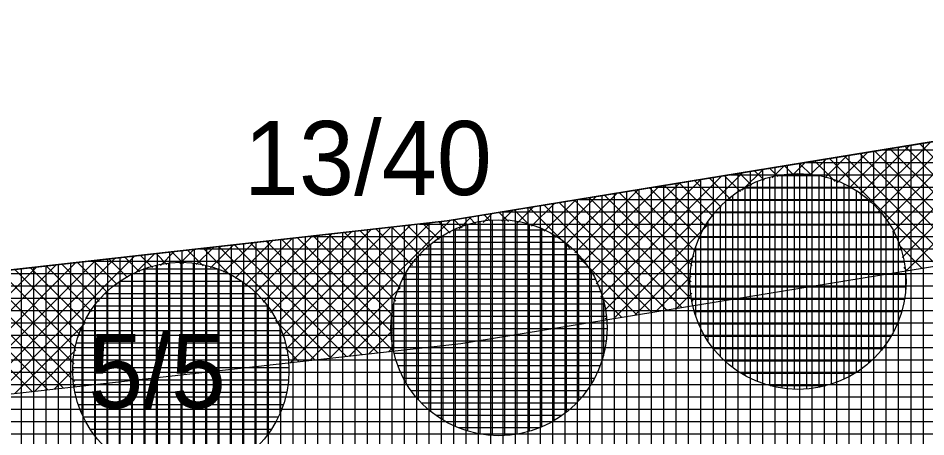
# Model space of a CAD drawing. Extents: x -566461 to -565198, y -1096301 to -1095707.
# Drawn here: x -565594.91 to -565580.22, y -1095872.26 to -1095865.47 of the extents above; entities that cross this region are included whole.
import ezdxf

# ---------------------------------------------------------------- set-up
doc = ezdxf.new("R2010")
doc.units = 0
for name, color, linetype in [('Vrstva 13', 7, 'Continuous'), ('Vrstva 40', 7, 'Continuous'), ('Vrstva 41', 7, 'Continuous'), ('Vrstva 42', 7, 'Continuous'), ('Vrstva 43', 7, 'Continuous'), ('Vrstva 44', 7, 'Continuous')]:
    doc.layers.add(name, color=color, linetype=linetype)

msp = doc.modelspace()

# ---------------------------------------------------------------- linework, layer by layer
at = {"layer": 'Vrstva 13'}
for p, q in [((-565587.97, -1095868.76), (-565569.62, -1095865.76)), ((-565610.5, -1095871.29), (-565587.97, -1095868.76))]:
    msp.add_line(p, q, dxfattribs=at)
at = {"layer": 'Vrstva 41'}
for p, q in [((-565580.604, -1095869.354), (-565578.455, -1095867.204)), ((-565580.538, -1095869.57), (-565578.117, -1095867.149)), ((-565580.862, -1095868.763), (-565579.469, -1095867.37)), ((-565580.757, -1095868.941), (-565579.131, -1095867.315)), ((-565580.67, -1095869.137), (-565578.793, -1095867.26)), ((-565581.125, -1095868.46), (-565580.145, -1095867.481)), ((-565580.985, -1095868.604), (-565579.807, -1095867.425)), ((-565578.577, -1095869.25), (-565580.318, -1095867.509)), ((-565581.648, -1095868.135), (-565581.16, -1095867.647)), ((-565581.455, -1095868.225), (-565580.822, -1095867.591)), ((-565579.55, -1095869.409), (-565581.291, -1095867.668)), ((-565581.281, -1095868.333), (-565580.484, -1095867.536)), ((-565579.307, -1095869.369), (-565581.048, -1095867.628)), ((-565579.064, -1095869.329), (-565580.805, -1095867.589)), ((-565578.82, -1095869.29), (-565580.561, -1095867.549)), ((-565582.375, -1095868.013), (-565582.174, -1095867.812)), ((-565582.099, -1095868.02), (-565581.836, -1095867.757)), ((-565581.688, -1095868.119), (-565582.02, -1095867.787)), ((-565581.861, -1095868.065), (-565581.498, -1095867.702)), ((-565580.036, -1095869.488), (-565581.777, -1095867.748)), ((-565579.793, -1095869.449), (-565581.534, -1095867.708)), ((-565583.191, -1095868.263), (-565582.85, -1095867.923)), ((-565582.839, -1095868.099), (-565582.992, -1095867.946)), ((-565582.615, -1095868.041), (-565582.749, -1095867.906)), ((-565582.707, -1095868.062), (-565582.512, -1095867.868)), ((-565582.36, -1095868.013), (-565582.506, -1095867.867)), ((-565582.065, -1095868.025), (-565582.263, -1095867.827)), ((-565585.555, -1095869.779), (-565583.865, -1095868.089)), ((-565585.479, -1095869.986), (-565583.527, -1095868.034)), ((-565585.426, -1095870.216), (-565583.188, -1095867.978)), ((-565583.532, -1095868.537), (-565583.965, -1095868.105)), ((-565583.385, -1095868.402), (-565583.722, -1095868.065)), ((-565583.221, -1095868.283), (-565583.479, -1095868.026)), ((-565583.04, -1095868.182), (-565583.236, -1095867.986)), ((-565585.902, -1095869.278), (-565584.879, -1095868.255)), ((-565585.77, -1095869.428), (-565584.541, -1095868.199)), ((-565585.654, -1095869.595), (-565584.203, -1095868.144)), ((-565583.875, -1095869.044), (-565584.694, -1095868.224)), ((-565583.778, -1095868.857), (-565584.451, -1095868.185)), ((-565583.664, -1095868.689), (-565584.208, -1095868.145)), ((-565586.216, -1095869.026), (-565585.555, -1095868.365)), ((-565586.051, -1095869.143), (-565585.217, -1095868.31)), ((-565583.989, -1095870.061), (-565585.666, -1095868.383)), ((-565584.021, -1095869.746), (-565585.423, -1095868.344)), ((-565584, -1095869.484), (-565585.18, -1095868.304)), ((-565583.949, -1095869.253), (-565584.937, -1095868.264)), ((-565586.829, -1095868.791), (-565586.57, -1095868.531)), ((-565585.981, -1095869.2), (-565586.639, -1095868.542)), ((-565586.601, -1095868.846), (-565586.232, -1095868.476)), ((-565586.399, -1095868.926), (-565585.893, -1095868.421)), ((-565584.655, -1095870.243), (-565586.396, -1095868.503)), ((-565584.412, -1095870.203), (-565586.153, -1095868.463)), ((-565584.169, -1095870.164), (-565585.91, -1095868.423)), ((-565587.777, -1095868.89), (-565587.584, -1095868.697)), ((-565587.388, -1095868.784), (-565587.246, -1095868.642)), ((-565587.261, -1095868.769), (-565587.368, -1095868.662)), ((-565586.977, -1095868.77), (-565587.125, -1095868.622)), ((-565587.086, -1095868.764), (-565586.908, -1095868.586)), ((-565586.625, -1095868.839), (-565586.882, -1095868.582)), ((-565590.581, -1095870.845), (-565588.562, -1095868.826)), ((-565590.51, -1095871.057), (-565588.244, -1095868.791)), ((-565590.192, -1095871.022), (-565587.922, -1095868.752)), ((-565588.26, -1095869.184), (-565588.612, -1095868.832)), ((-565588.099, -1095869.062), (-565588.358, -1095868.804)), ((-565587.922, -1095868.957), (-565588.103, -1095868.775)), ((-565587.725, -1095868.87), (-565587.854, -1095868.741)), ((-565587.508, -1095868.805), (-565587.611, -1095868.701)), ((-565585.271, -1095870.343), (-565583.767, -1095868.839)), ((-565590.945, -1095870.078), (-565589.837, -1095868.97)), ((-565590.826, -1095870.242), (-565589.518, -1095868.934)), ((-565590.724, -1095870.422), (-565589.199, -1095868.898)), ((-565590.641, -1095870.622), (-565588.881, -1095868.862)), ((-565588.8, -1095870.058), (-565589.883, -1095868.975)), ((-565588.731, -1095869.845), (-565589.629, -1095868.946)), ((-565588.64, -1095869.653), (-565589.375, -1095868.918)), ((-565588.531, -1095869.479), (-565589.121, -1095868.889)), ((-565588.403, -1095869.323), (-565588.866, -1095868.861)), ((-565591.59, -1095869.591), (-565591.111, -1095869.113)), ((-565591.402, -1095869.687), (-565590.793, -1095869.077)), ((-565591.233, -1095869.8), (-565590.474, -1095869.041)), ((-565589.345, -1095870.927), (-565591.155, -1095869.118)), ((-565591.081, -1095869.931), (-565590.155, -1095869.005)), ((-565589.091, -1095870.898), (-565590.901, -1095869.089)), ((-565588.837, -1095870.87), (-565590.646, -1095869.061)), ((-565588.854, -1095870.57), (-565590.392, -1095869.032)), ((-565588.847, -1095870.294), (-565590.138, -1095869.003)), ((-565580.279, -1095869.528), (-565580.669, -1095869.138)), ((-565592.61, -1095869.48), (-565592.386, -1095869.256)), ((-565592.237, -1095869.449), (-565592.426, -1095869.26)), ((-565592.295, -1095869.448), (-565592.067, -1095869.22)), ((-565591.918, -1095869.485), (-565592.172, -1095869.232)), ((-565592.032, -1095869.468), (-565591.748, -1095869.184)), ((-565591.471, -1095869.65), (-565591.918, -1095869.203)), ((-565591.799, -1095869.518), (-565591.43, -1095869.149)), ((-565589.854, -1095870.984), (-565591.663, -1095869.175)), ((-565589.6, -1095870.955), (-565591.409, -1095869.146)), ((-565595.681, -1095871.137), (-565593.979, -1095869.435)), ((-565595.638, -1095871.377), (-565593.66, -1095869.399)), ((-565595.606, -1095871.628), (-565593.342, -1095869.363)), ((-565595.288, -1095871.592), (-565593.023, -1095869.327)), ((-565593.466, -1095869.918), (-565593.952, -1095869.432)), ((-565593.312, -1095869.789), (-565593.698, -1095869.403)), ((-565593.141, -1095869.677), (-565593.443, -1095869.375)), ((-565592.951, -1095869.584), (-565593.189, -1095869.346)), ((-565593.035, -1095869.623), (-565592.704, -1095869.292)), ((-565592.74, -1095869.512), (-565592.935, -1095869.318)), ((-565592.506, -1095869.464), (-565592.681, -1095869.289)), ((-565584.899, -1095870.283), (-565585.84, -1095869.341)), ((-565584.933, -1095870.288), (-565583.968, -1095869.323)), ((-565595.84, -1095870.73), (-565594.616, -1095869.506)), ((-565595.75, -1095870.923), (-565594.297, -1095869.471)), ((-565593.975, -1095870.823), (-565595.223, -1095869.575)), ((-565593.912, -1095870.603), (-565594.969, -1095869.546)), ((-565593.827, -1095870.405), (-565594.715, -1095869.517)), ((-565593.724, -1095870.226), (-565594.461, -1095869.489)), ((-565593.603, -1095870.063), (-565594.206, -1095869.46)), ((-565580.522, -1095869.568), (-565580.575, -1095869.515)), ((-565594.687, -1095871.525), (-565596.495, -1095869.717)), ((-565594.433, -1095871.496), (-565596.241, -1095869.689)), ((-565594.178, -1095871.468), (-565595.986, -1095869.66)), ((-565594.003, -1095871.361), (-565595.732, -1095869.632)), ((-565594.007, -1095871.074), (-565595.478, -1095869.603)), ((-565584.595, -1095870.233), (-565584.017, -1095869.655)), ((-565589.873, -1095870.986), (-565588.73, -1095869.843)), ((-565585.142, -1095870.322), (-565585.479, -1095869.985)), ((-565584.257, -1095870.178), (-565584.01, -1095869.931)), ((-565589.555, -1095870.95), (-565588.836, -1095870.232)), ((-565594.969, -1095871.556), (-565593.837, -1095870.425)), ((-565590.109, -1095871.012), (-565590.75, -1095870.371)), ((-565585.385, -1095870.362), (-565585.41, -1095870.337)), ((-565589.236, -1095870.915), (-565588.856, -1095870.534)), ((-565594.651, -1095871.521), (-565593.98, -1095870.85)), ((-565590.363, -1095871.041), (-565590.585, -1095870.818)), ((-565588.918, -1095870.879), (-565588.829, -1095870.791)), ((-565594.332, -1095871.485), (-565594.012, -1095871.165)), ((-565594.014, -1095871.45), (-565593.992, -1095871.428))]:
    msp.add_line(p, q, dxfattribs=at)
at = {"layer": 'Vrstva 42'}
msp.add_lwpolyline([(-565642.21, -1095870.56), (-565642.251, -1095872.566), (-565630.414, -1095873.721), (-565610.455, -1095873.29), (-565587.747, -1095870.748), (-565569.297, -1095867.734), (-565519.622, -1095865.105), (-565519.36, -1095863.08), (-565569.62, -1095865.76), (-565587.97, -1095868.76), (-565610.5, -1095871.29), (-565630.22, -1095871.73)], close=True, dxfattribs=at)
at = {"layer": 'Vrstva 43'}
for p, q in [((-565580.26, -1095882.47), (-565580.26, -1095867.5)), ((-565581.26, -1095882.858), (-565581.26, -1095867.663)), ((-565581.06, -1095882.825), (-565581.06, -1095867.63)), ((-565580.936, -1095867.61), (-565519.947, -1095867.61)), ((-565580.86, -1095882.792), (-565580.86, -1095867.598)), ((-565580.66, -1095882.759), (-565580.66, -1095867.565)), ((-565580.46, -1095882.727), (-565580.46, -1095867.532)), ((-565582.159, -1095867.81), (-565519.973, -1095867.81)), ((-565582.06, -1095882.989), (-565582.06, -1095867.794)), ((-565581.86, -1095882.956), (-565581.86, -1095867.761)), ((-565581.66, -1095882.923), (-565581.66, -1095867.728)), ((-565581.46, -1095882.89), (-565581.46, -1095867.696)), ((-565583.06, -1095883.152), (-565583.06, -1095867.957)), ((-565582.86, -1095883.119), (-565582.86, -1095867.925)), ((-565582.66, -1095883.087), (-565582.66, -1095867.892)), ((-565582.46, -1095883.054), (-565582.46, -1095867.859)), ((-565582.26, -1095883.021), (-565582.26, -1095867.826)), ((-565583.86, -1095883.283), (-565583.86, -1095868.088)), ((-565583.66, -1095883.25), (-565583.66, -1095868.055)), ((-565583.46, -1095883.218), (-565583.46, -1095868.023)), ((-565583.383, -1095868.01), (-565519.999, -1095868.01)), ((-565583.26, -1095883.185), (-565583.26, -1095867.99)), ((-565584.86, -1095883.447), (-565584.86, -1095868.252)), ((-565584.66, -1095883.414), (-565584.66, -1095868.219)), ((-565584.606, -1095868.21), (-565520.025, -1095868.21)), ((-565584.46, -1095883.381), (-565584.46, -1095868.186)), ((-565584.26, -1095883.348), (-565584.26, -1095868.153)), ((-565584.06, -1095883.316), (-565584.06, -1095868.121)), ((-565585.66, -1095883.577), (-565585.66, -1095868.382)), ((-565585.46, -1095883.545), (-565585.46, -1095868.35)), ((-565585.26, -1095883.512), (-565585.26, -1095868.317)), ((-565585.06, -1095883.479), (-565585.06, -1095868.284)), ((-565586.66, -1095883.703), (-565586.66, -1095868.546)), ((-565586.46, -1095883.681), (-565586.46, -1095868.513)), ((-565586.26, -1095883.658), (-565586.26, -1095868.48)), ((-565586.06, -1095883.636), (-565586.06, -1095868.448)), ((-565585.86, -1095883.61), (-565585.86, -1095868.415)), ((-565585.829, -1095868.41), (-565520.05, -1095868.41)), ((-565587.46, -1095883.793), (-565587.46, -1095868.677)), ((-565587.26, -1095883.771), (-565587.26, -1095868.644)), ((-565587.06, -1095883.748), (-565587.06, -1095868.611)), ((-565587.053, -1095868.61), (-565520.076, -1095868.61)), ((-565586.86, -1095883.726), (-565586.86, -1095868.579)), ((-565588.66, -1095883.928), (-565588.66, -1095868.837)), ((-565588.46, -1095883.906), (-565588.46, -1095868.815)), ((-565588.415, -1095868.81), (-565520.102, -1095868.81)), ((-565588.26, -1095883.883), (-565588.26, -1095868.793)), ((-565588.06, -1095883.861), (-565588.06, -1095868.77)), ((-565587.86, -1095883.838), (-565587.86, -1095868.742)), ((-565587.66, -1095883.816), (-565587.66, -1095868.709)), ((-565589.86, -1095883.865), (-565589.86, -1095868.972)), ((-565589.66, -1095883.836), (-565589.66, -1095868.95)), ((-565589.46, -1095883.807), (-565589.46, -1095868.927)), ((-565589.26, -1095883.996), (-565589.26, -1095868.905)), ((-565589.06, -1095883.973), (-565589.06, -1095868.882)), ((-565588.86, -1095883.951), (-565588.86, -1095868.86)), ((-565591.26, -1095884.069), (-565591.26, -1095869.129)), ((-565591.06, -1095884.04), (-565591.06, -1095869.107)), ((-565590.86, -1095884.011), (-565590.86, -1095869.085)), ((-565590.66, -1095883.981), (-565590.66, -1095869.062)), ((-565590.46, -1095883.952), (-565590.46, -1095869.04)), ((-565590.26, -1095883.923), (-565590.26, -1095869.017)), ((-565590.196, -1095869.01), (-565520.128, -1095869.01)), ((-565590.06, -1095883.894), (-565590.06, -1095868.995)), ((-565592.66, -1095884.272), (-565592.66, -1095869.287)), ((-565592.46, -1095884.243), (-565592.46, -1095869.264)), ((-565592.26, -1095884.214), (-565592.26, -1095869.242)), ((-565592.06, -1095884.185), (-565592.06, -1095869.219)), ((-565591.977, -1095869.21), (-565520.154, -1095869.21)), ((-565591.86, -1095884.156), (-565591.86, -1095869.197)), ((-565591.66, -1095884.127), (-565591.66, -1095869.174)), ((-565591.46, -1095884.098), (-565591.46, -1095869.152)), ((-565593.86, -1095884.446), (-565593.86, -1095869.421)), ((-565593.758, -1095869.41), (-565520.18, -1095869.41)), ((-565593.66, -1095884.417), (-565593.66, -1095869.399)), ((-565593.46, -1095884.388), (-565593.46, -1095869.376)), ((-565593.26, -1095884.359), (-565593.26, -1095869.354)), ((-565593.06, -1095884.33), (-565593.06, -1095869.332)), ((-565592.86, -1095884.301), (-565592.86, -1095869.309)), ((-565594.86, -1095884.592), (-565594.86, -1095869.534)), ((-565594.66, -1095884.563), (-565594.66, -1095869.511)), ((-565594.46, -1095884.534), (-565594.46, -1095869.489)), ((-565594.26, -1095884.505), (-565594.26, -1095869.466)), ((-565594.06, -1095884.476), (-565594.06, -1095869.444)), ((-565595.539, -1095869.61), (-565520.206, -1095869.61)), ((-565597.32, -1095869.81), (-565520.232, -1095869.81)), ((-565599.101, -1095870.01), (-565520.258, -1095870.01)), ((-565600.882, -1095870.21), (-565520.284, -1095870.21)), ((-565602.663, -1095870.41), (-565520.31, -1095870.41)), ((-565604.445, -1095870.61), (-565520.335, -1095870.61)), ((-565606.226, -1095870.81), (-565520.361, -1095870.81)), ((-565608.007, -1095871.01), (-565520.387, -1095871.01)), ((-565609.788, -1095871.21), (-565520.413, -1095871.21)), ((-565615.878, -1095871.41), (-565520.439, -1095871.41)), ((-565624.842, -1095871.61), (-565520.465, -1095871.61)), ((-565642.236, -1095871.81), (-565520.491, -1095871.81)), ((-565642.24, -1095872.01), (-565520.517, -1095872.01)), ((-565642.244, -1095872.21), (-565520.543, -1095872.21))]:
    msp.add_line(p, q, dxfattribs=at)
msp.add_lwpolyline([(-565639.56, -1095885.89), (-565630.78, -1095886.75), (-565609.49, -1095886.27), (-565595.88, -1095884.74), (-565585.92, -1095883.62), (-565568.01, -1095880.69), (-565521.32, -1095878.21), (-565519.36, -1095863.08), (-565522.03, -1095863.23), (-565569.62, -1095865.76), (-565587.97, -1095868.76), (-565610.5, -1095871.29), (-565630.22, -1095871.73), (-565642.21, -1095870.56), (-565642.52, -1095885.6), (-565645.08, -1096008.78), (-565642.11, -1096010.51)], close=True, dxfattribs=at)
at = {"layer": 'Vrstva 44'}
for p, q in [((-565582.75, -1095868.052), (-565582.75, -1095871.428)), ((-565581.921, -1095868.03), (-565582.654, -1095868.03)), ((-565582.55, -1095868.011), (-565582.55, -1095871.469)), ((-565582.35, -1095867.993), (-565582.35, -1095871.488)), ((-565582.15, -1095867.997), (-565582.15, -1095871.483)), ((-565581.95, -1095868.024), (-565581.95, -1095871.455)), ((-565581.75, -1095868.076), (-565581.75, -1095871.403)), ((-565581.409, -1095868.23), (-565583.171, -1095868.23)), ((-565583.15, -1095868.218), (-565583.15, -1095871.262)), ((-565582.95, -1095868.121), (-565582.95, -1095871.36)), ((-565581.55, -1095868.156), (-565581.55, -1095871.325)), ((-565583.35, -1095868.348), (-565583.35, -1095871.131)), ((-565581.35, -1095868.265), (-565581.35, -1095871.214)), ((-565583.55, -1095868.528), (-565583.55, -1095870.952)), ((-565581.133, -1095868.43), (-565583.448, -1095868.43)), ((-565581.15, -1095868.414), (-565581.15, -1095871.066)), ((-565580.938, -1095868.63), (-565583.64, -1095868.63)), ((-565580.95, -1095868.615), (-565580.95, -1095870.863)), ((-565587.64, -1095868.817), (-565587.64, -1095872.163)), ((-565587.44, -1095868.768), (-565587.44, -1095872.21)), ((-565587.24, -1095868.745), (-565587.24, -1095872.235)), ((-565587.04, -1095868.744), (-565587.04, -1095872.237)), ((-565586.84, -1095868.766), (-565586.84, -1095872.216)), ((-565586.64, -1095868.811), (-565586.64, -1095872.168)), ((-565580.798, -1095868.83), (-565583.784, -1095868.83)), ((-565583.75, -1095868.779), (-565583.75, -1095870.702)), ((-565586.382, -1095868.91), (-565587.879, -1095868.91)), ((-565587.84, -1095868.893), (-565587.84, -1095872.087)), ((-565586.44, -1095868.883), (-565586.44, -1095872.096)), ((-565586.24, -1095868.986), (-565586.24, -1095871.996)), ((-565580.75, -1095868.91), (-565580.75, -1095870.567)), ((-565588.24, -1095869.139), (-565588.24, -1095871.841)), ((-565586.056, -1095869.11), (-565588.205, -1095869.11)), ((-565588.04, -1095868.996), (-565588.04, -1095871.983)), ((-565586.04, -1095869.122), (-565586.04, -1095871.857)), ((-565580.691, -1095869.03), (-565583.888, -1095869.03)), ((-565580.617, -1095869.23), (-565583.962, -1095869.23)), ((-565583.95, -1095869.191), (-565583.95, -1095870.292)), ((-565592.28, -1095869.431), (-565592.28, -1095872.928)), ((-565588.44, -1095869.33), (-565588.44, -1095871.649)), ((-565585.84, -1095869.31), (-565588.421, -1095869.31)), ((-565585.84, -1095869.31), (-565585.84, -1095871.672)), ((-565580.57, -1095869.43), (-565584.011, -1095869.43)), ((-565591.675, -1095869.54), (-565592.888, -1095869.54)), ((-565592.88, -1095869.537), (-565592.88, -1095872.822)), ((-565592.68, -1095869.478), (-565592.68, -1095872.883)), ((-565592.48, -1095869.443), (-565592.48, -1095872.918)), ((-565592.08, -1095869.442), (-565592.08, -1095872.917)), ((-565591.88, -1095869.478), (-565591.88, -1095872.882)), ((-565591.68, -1095869.538), (-565591.68, -1095872.824)), ((-565585.681, -1095869.51), (-565588.578, -1095869.51)), ((-565585.64, -1095869.576), (-565585.64, -1095871.407)), ((-565580.55, -1095869.568), (-565580.55, -1095869.91)), ((-565593.08, -1095869.624), (-565593.08, -1095872.736)), ((-565591.48, -1095869.625), (-565591.48, -1095872.735)), ((-565585.566, -1095869.71), (-565588.695, -1095869.71)), ((-565588.64, -1095869.606), (-565588.64, -1095871.373)), ((-565580.545, -1095869.63), (-565584.036, -1095869.63)), ((-565593.28, -1095869.746), (-565593.28, -1095872.614)), ((-565591.287, -1095869.74), (-565593.271, -1095869.74)), ((-565591.28, -1095869.746), (-565591.28, -1095872.614)), ((-565580.544, -1095869.83), (-565584.037, -1095869.83)), ((-565591.046, -1095869.94), (-565593.512, -1095869.94)), ((-565593.48, -1095869.907), (-565593.48, -1095872.453)), ((-565591.08, -1095869.908), (-565591.08, -1095872.452)), ((-565585.481, -1095869.91), (-565588.781, -1095869.91)), ((-565590.875, -1095870.14), (-565593.687, -1095870.14)), ((-565593.68, -1095870.132), (-565593.68, -1095872.227)), ((-565590.88, -1095870.133), (-565590.88, -1095872.23)), ((-565588.84, -1095870.127), (-565588.84, -1095870.855)), ((-565585.422, -1095870.11), (-565588.837, -1095870.11)), ((-565585.44, -1095870.043), (-565585.44, -1095870.944)), ((-565580.564, -1095870.03), (-565584.014, -1095870.03)), ((-565585.391, -1095870.31), (-565588.869, -1095870.31)), ((-565580.612, -1095870.23), (-565583.968, -1095870.23)), ((-565590.745, -1095870.34), (-565593.813, -1095870.34)), ((-565580.684, -1095870.43), (-565583.897, -1095870.43)), ((-565590.653, -1095870.54), (-565593.907, -1095870.54)), ((-565593.88, -1095870.475), (-565593.88, -1095871.888)), ((-565590.68, -1095870.472), (-565590.68, -1095871.884)), ((-565585.382, -1095870.51), (-565588.878, -1095870.51)), ((-565590.588, -1095870.74), (-565593.973, -1095870.74)), ((-565585.396, -1095870.71), (-565588.865, -1095870.71)), ((-565580.784, -1095870.63), (-565583.796, -1095870.63)), ((-565580.923, -1095870.83), (-565583.657, -1095870.83)), ((-565590.548, -1095870.94), (-565594.013, -1095870.94)), ((-565585.432, -1095870.91), (-565588.828, -1095870.91)), ((-565581.108, -1095871.03), (-565583.47, -1095871.03)), ((-565590.531, -1095871.14), (-565594.028, -1095871.14)), ((-565585.494, -1095871.11), (-565588.765, -1095871.11)), ((-565590.539, -1095871.34), (-565594.021, -1095871.34)), ((-565585.586, -1095871.31), (-565588.674, -1095871.31)), ((-565581.373, -1095871.23), (-565583.205, -1095871.23)), ((-565581.837, -1095871.43), (-565582.741, -1095871.43)), ((-565590.569, -1095871.54), (-565593.991, -1095871.54)), ((-565585.71, -1095871.51), (-565588.551, -1095871.51)), ((-565590.624, -1095871.74), (-565593.938, -1095871.74)), ((-565585.878, -1095871.71), (-565588.382, -1095871.71)), ((-565586.109, -1095871.91), (-565588.149, -1095871.91)), ((-565590.704, -1095871.94), (-565593.855, -1095871.94)), ((-565590.819, -1095872.14), (-565593.741, -1095872.14)), ((-565586.473, -1095872.11), (-565587.791, -1095872.11))]:
    msp.add_line(p, q, dxfattribs=at)
for centre in [(-565582.29, -1095869.74), (-565587.13, -1095870.49), (-565592.28, -1095871.18)]:
    msp.add_circle(centre, 1.75, dxfattribs=at)

# ---------------------------------------------------------------- texts
at = {"layer": 'Vrstva 40'}
for s, p in [('13/40', (-565591.26, -1095868.34)), ('5/5', (-565593.78, -1095871.79))]:
    msp.add_text(s, height=1.2, dxfattribs=at).set_placement(p)

doc.saveas('drawing.dxf')
